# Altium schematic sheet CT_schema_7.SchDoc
size 374 x 245 mm
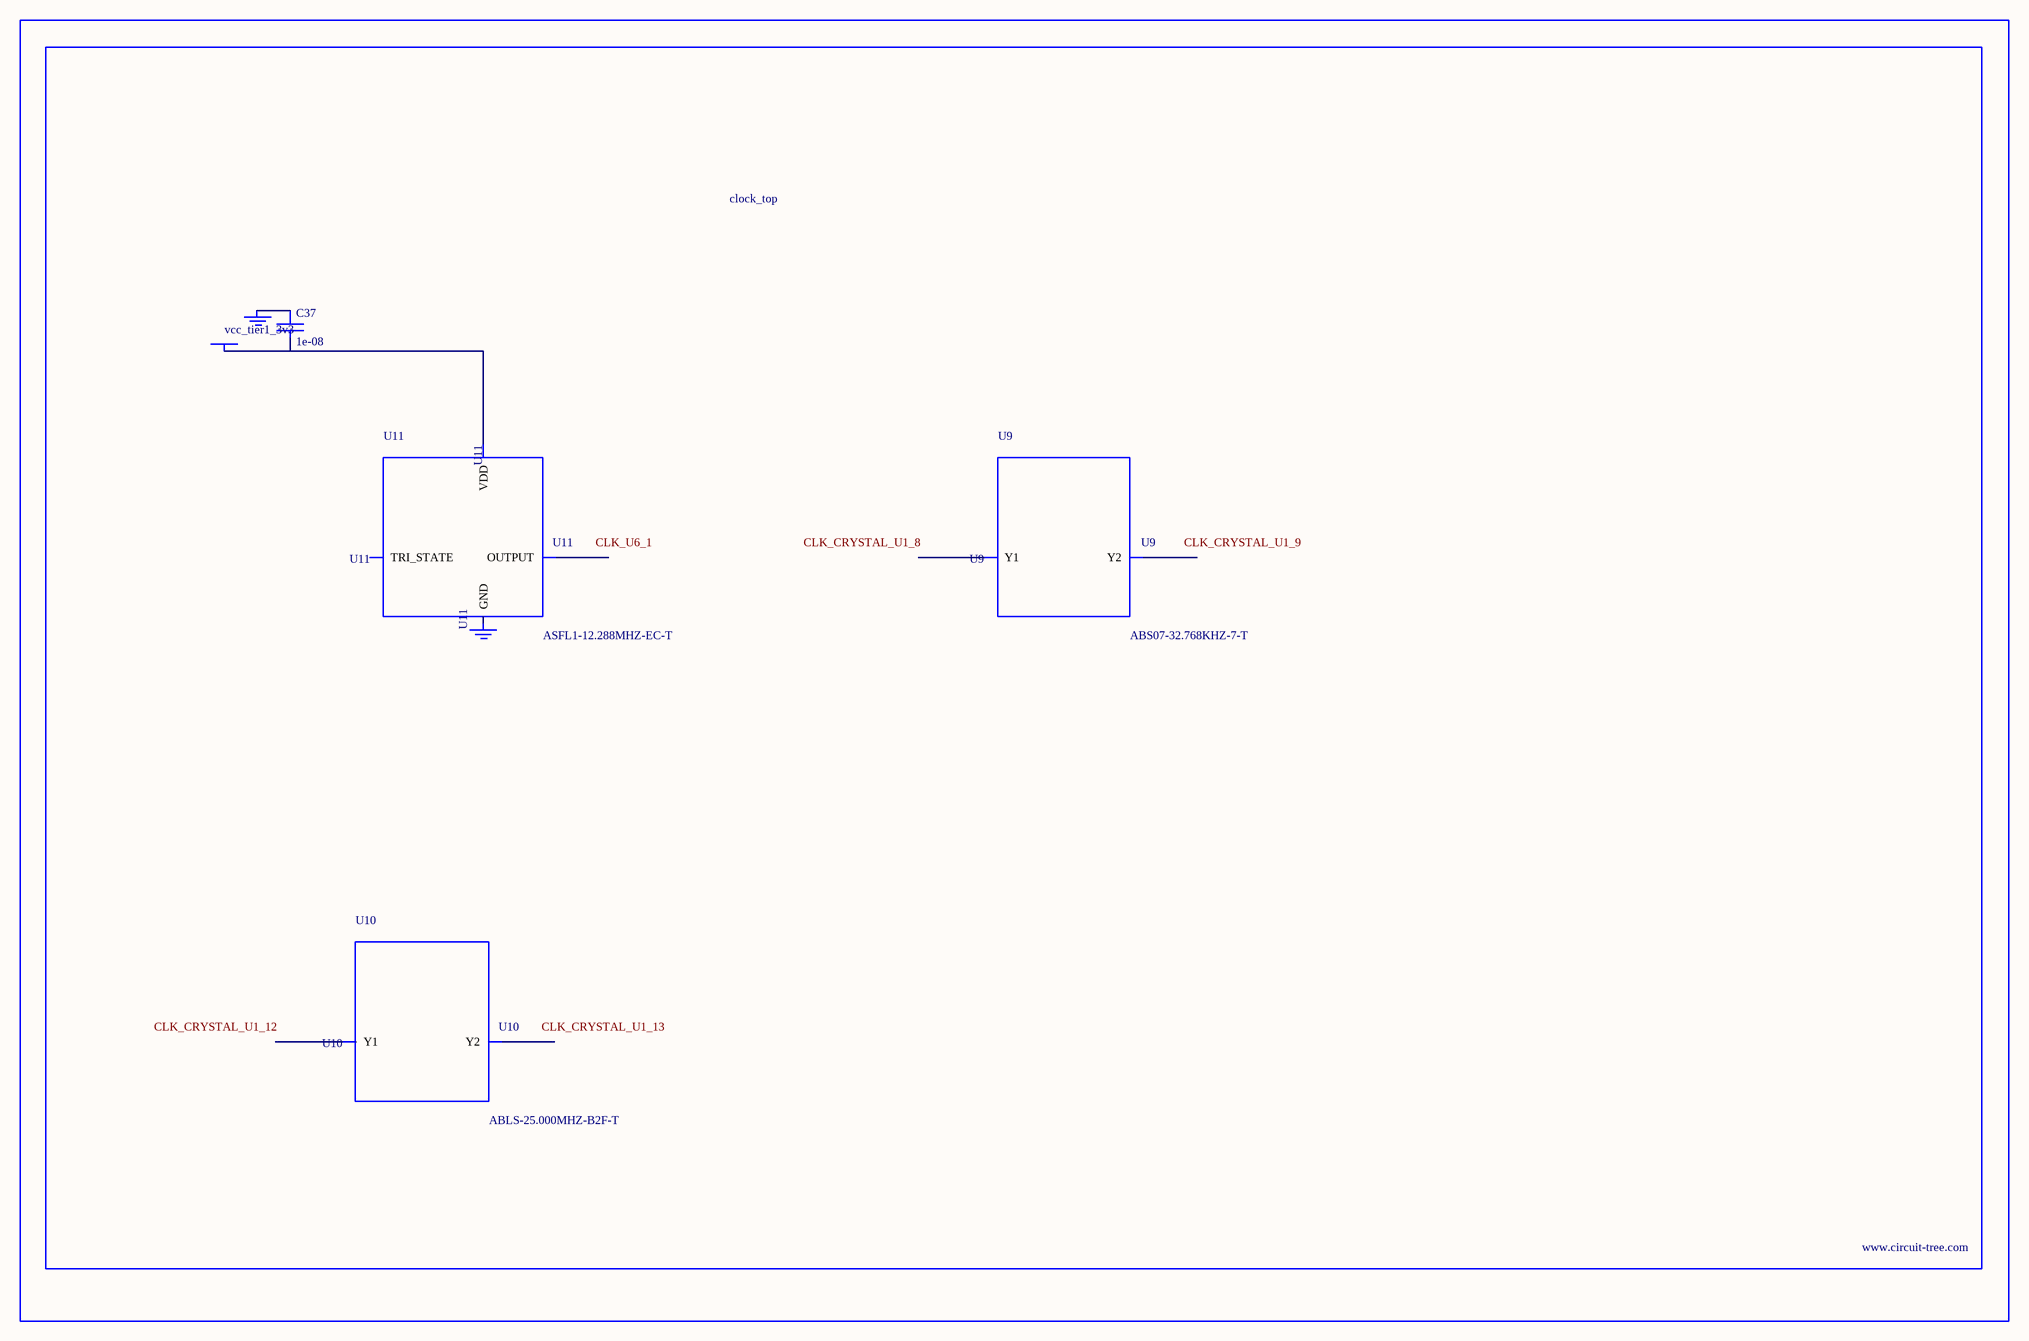
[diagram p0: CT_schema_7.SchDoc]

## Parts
BORDER6  (no value)
C37  1e-08  [C0402]
GND_INSTANCE_6_0  (no value)
GND_INSTANCE_6_1  (no value)
POWER_INSTANCE_6_0  vcc_tier1_3v3
U9  ABS07-32.768KHZ-7-T  [ABS07-32.768KHZ-7-T]
U10  ABLS-25.000MHZ-B2F-T  [ABLS-25.000MHZ-B2F-T]
U11  ASFL1-12.288MHZ-EC-T  [ASFL1]

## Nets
NetC37_1: C37.1 GND_INSTANCE_6_0.0(GND)
NetC37_2: C37.2 POWER_INSTANCE_6_0.0(PWR) U11.4(VDD)

Not connected (* = marked no-connect by the designer): GND_INSTANCE_6_1 0(GND); U9 1(Y1) 2(Y2); U10 1(Y1) 2(Y2); U11 1(TRI_STATE) 2(GND) 3(OUTPUT)

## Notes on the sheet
- Labels drawn without touching a wire or pin: CLK_CRYSTAL_U1_8, CLK_CRYSTAL_U1_9, CLK_CRYSTAL_U1_12, CLK_CRYSTAL_U1_13, CLK_U6_1

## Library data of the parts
BORDER6 = BORDER_PAGE6
C37 = C0402C103K3RAC
GND_INSTANCE_6_0 GND_INSTANCE_6_1 = GND
POWER_INSTANCE_6_0 = PWR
